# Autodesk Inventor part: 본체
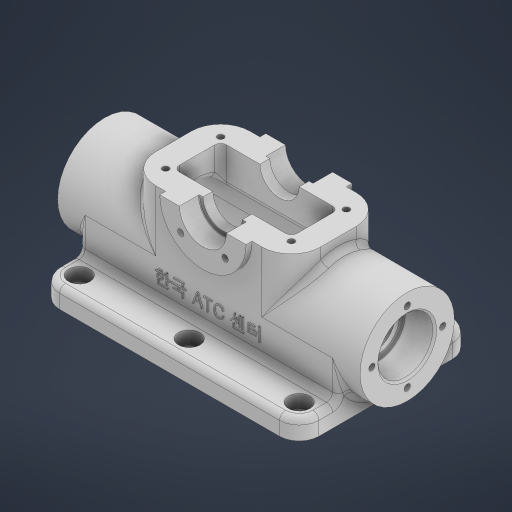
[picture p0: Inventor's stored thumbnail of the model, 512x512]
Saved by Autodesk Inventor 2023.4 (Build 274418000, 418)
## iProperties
Created: 2024-06
Part Number: 본체
Material: 알루미늄 6061
Document SubType Name: Modeling
Designer: Edu03
Density: 2.7 g/cm^3
Appearance: 기본값
Mass: 551.012 g
Surface Area: 614.152 cm^2
Volume: 204.079 cm^3
Author: Edu03
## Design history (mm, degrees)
sketch "스케치1"
  geometry: L1 (-94.718, 0)-(94.718, 0); L2 (-77, 24)-(-77, 14); L3 (-77, 14)-(-62, 14); L4 (-62, 14)-(-62, 11); L5 (-62, 11)-(-60, 11); L6 (-60, 11)-(-60, 18); L7 (-60, 18)-(60, 18); L8 (60, 18)-(60, 11); L9 (60, 11)-(62, 11); L10 (62, 11)-(62, 14); L11 (62, 14)-(77, 14); L12 (77, 14)-(77, 24); L13 (77, 24)-(-77, 24); 3 further points
  constraints: 26 end point, 9 perpendicular, 4 point on line, 2 midpoint, 1 coincident, 1 collinear, 1 horizontal, 1 vertical, 1 vertical alignment
  dimensions: "d0" = 154 distance of L12.end L2.start; "d1" = 15 distance of L2.end L3.end; "d2" = 15 distance of L10.end L11.end; "d3" = 120 distance of L6.end L7.end; "d4" = 48 diameter of L13 L1; "d5" = 22 diameter of L5 L1; "d6" = 28 diameter of L3 L1; "d7" = 6 distance between parallel lines of L13 L7
revolve "회전1" sketch "스케치1" stored, may be unused: angle "d8" = 90 deg
node "작업 평면1"
sketch "스케치2"
  geometry: L1 (44, -18)-(44, -28); L2 (44, -28)-(-44, -28); L3 (-44, -28)-(-44, -18); L4 (-24, -18)-(-24, 0); L5 (24, -18)-(24, 0); L6 (24, -18)-(44, -18); L7 (-44, -18)-(-24, -18); A1 r 24 centre (0, 0) between (-24, 0) and (24, 0) reference; 3 further points
  constraints: 14 end point, 3 parallel, 2 horizontal, 2 horizontal alignment, 2 perpendicular, 2 point on circle, 2 tangent, 2 vertical, 2 vertical alignment, 1 midpoint
  dimensions: "d10" = 88 distance of L1.end L2.end; "d12" = 28 distance from line of A1.centre L2; "d13" = 10 distance between parallel lines of L2 L6
extrude "돌출1" join sketch "스케치2" distance "d14" = 132; taper "d15" = 0 deg
node "작업 평면2"
sketch "스케치3"
  geometry: L1 (44, -28)-(-44, -28) reference; L2 (-18, -28)-(-18, 0); L3 (18, -28)-(18, 0); A1 r 18 centre (0, 0) between (18, 0) and (-18, 0) reference; 1 further point
  constraints: 4 end point, 2 point on circle, 2 point on line, 2 tangent, 2 vertical
extrude "돌출2" cut sketch "스케치3" distance "d17" = 120; taper "d18" = 0 deg
node "작업 평면3"
node "작업 평면4"
sketch "스케치5"
  geometry: L1 (24, 20)-(108, 20); L2 (108, 20)-(108, 68); L3 (108, 68)-(24, 68); L4 (24, 68)-(24, 20); L5 (143, 20)-(143, 68) reference; L6 (-11, 20)-(-11, 68) reference; L7 (0, 20)-(132, 20) reference; L8 (0, 20)-(0, 68) reference; L9 (0, 68)-(132, 68) reference; L10 (132, 68)-(132, 20) reference; 3 further points
  constraints: 8 end point, 2 midpoint, 2 parallel, 1 horizontal, 1 horizontal alignment, 1 perpendicular, 1 point on line, 1 vertical alignment
  dimensions: "d22" = 84 distance of L1.start L1.end
extrude "돌출3" join sketch "스케치5" stored distance "d24" = 120; taper "d25" = 0 deg
sketch "스케치6"
  geometry: L1 (36, -56)-(96, -56); L2 (96, -56)-(96, -32); L3 (96, -32)-(36, -32); L4 (36, -32)-(36, -56); L5 (36, -56)-(96, -32); L6 (96, -56)-(36, -32); 1 further point
  constraints: 12 end point, 2 midpoint, 2 parallel, 1 horizontal, 1 perpendicular
  dimensions: "d26" = 60 distance of L2.end L3.end; "d27" = 24 distance between parallel lines of L3 L1
extrude "돌출4" cut sketch "스케치6" extent not by distance; stored distance "d28" = 10; taper "d29" = 0 deg
sketch "스케치9"
  geometry: L1 (36, 49)-(96, 49) reference; C1 r 22 at (66, 49); 3 further points
  constraints: 1 centre point, 1 midpoint
  dimensions: "d37" = 44 diameter of C1
extrude "돌출5" join sketch "스케치9" distance "d38" = 3; taper "d39" = 0 deg
sketch "스케치11"
  geometry: A1 r 22 centre (66, 49) between (44, 49) and (88, 49) reference; 2 further points
  constraints: 1 coincident
hole "구멍2" sketch "스케치11" at (66, 49) diameter "d40" = 20; stored, may be unused: countersink angle "d44" = 90 deg, drill point angle "d46" = 0 deg; dims "d41" = 6, "d42" = 24, "d43" = 10, "d45" = 8
sketch "스케치12" dims "d47" = 32
  geometry: L1 (66, 49)-(54.686, 37.686); L2 (66, 49)-(66, 53.677); A1 r 12 centre (66, 49) between (54, 49) and (78, 49) reference; 2 further points
  constraints: 4 end point, 1 coincident, 1 vertical, 3 other
  dimensions: "d48" = 45 deg angle of L2 L1
hole "구멍3" sketch "스케치12" at (54.686, 37.686) diameter "d49" = 3.242; stored, may be unused: countersink angle "d53" = 90 deg, drill point angle "d55" = 118 deg; dims "d50" = 8, "d51" = 24, "d52" = 10, "d54" = 10
sketch "스케치13"
  geometry: L1 (34, -30)-(98, -30); L2 (98, -30)-(98, -58); L3 (98, -58)-(34, -58); L4 (34, -58)-(34, -30); L5 (54, -17)-(78, -17) reference; L6 (108, -20)-(108, -68) reference; 5 further points
  constraints: 8 end point, 4 midpoint, 2 parallel, 1 horizontal, 1 horizontal alignment, 1 perpendicular, 1 vertical alignment
  dimensions: "d56" = 28 distance of L1.end L2.end; "d57" = 64 distance of L1.start L1.end
hole "구멍4" sketch "스케치13" at (34, -58), (98, -58), (98, -30), (34, -30) diameter "d58" = 3.242; stored, may be unused: countersink angle "d62" = 90 deg, drill point angle "d64" = 118 deg; dims "d59" = 8, "d60" = 4, "d61" = 2, "d63" = 10
sketch "스케치14"
  geometry: A1 r 18 centre (0, 0) between (12, 13.416) and (-12, 13.416); A2 r 18 centre (0, 0) between (12, 13.416) and (-12, 13.416) reference; 2 further points
  constraints: 1 centre point, 1 coincident, 1 point on circle, 1 vertical alignment
  dimensions: "d65" = 36 diameter of A1
hole "구멍5" sketch "스케치14" at (0, 18) diameter "d66" = 3.242; stored, may be unused: countersink angle "d70" = 90 deg, drill point angle "d72" = 118 deg; dims "d67" = 8, "d68" = 4, "d69" = 2, "d71" = 10
sketch "스케치15" dims "d76" = 36
  geometry: 3 further points
  constraints: 2 vertical alignment, 1 coincident, 2 other
hole "구멍6" sketch "스케치15" at (0, 18) diameter "d77" = 3.242; stored, may be unused: countersink angle "d81" = 90 deg, drill point angle "d83" = 118 deg; dims "d78" = 8, "d79" = 4, "d80" = 2, "d82" = 10
fillet "모깎기1" dims "d87" = 3
fillet "모깎기2" dims "d88" = 3
sketch "스케치16"
  geometry: L1 (10, 10)-(122, 10); 2 further points
  constraints: 2 end point, 1 horizontal, 1 midpoint, 1 vertical alignment
  dimensions: "d89" = 112 distance of L1.start L1.end; "d90" = 34 distance from line of point (66, 44) L1
hole "구멍7" sketch "스케치16" at (10, 10), (66, 10), (122, 10) diameter "d91" = 6.6; stored, may be unused: countersink angle "d95" = 90 deg, drill point angle "d97" = 0 deg; dims "d92" = 8, "d93" = 11, "d94" = 6.6, "d96" = 8
fillet "모깎기3" dims "d98" = 10
fillet "모깎기4" dims "d99" = 3
sketch "스케치17"
  geometry: L1 (24, -28)-(14, -28) reference; 2 further points
  constraints: 1 vertical alignment, 1 other
  dimensions: "d100" = 20 distance from line of L1 point (-42, -8)
feature "엠보싱1" sketch "스케치17" dims "d0" = 154, "d1" = 15, "d2" = 15, "d3" = 120, "d4" = 48, "d5" = 22, "d6" = 28, "d7" = 6, "d101" = 0.5, "d102" = 0
fillet "모깎기5" dims "d103" = 3
fillet "모깎기6" dims "d104" = 3
fillet "모깎기7" dims "d105" = 15
fillet "모깎기8" dims "d106" = 3
chamfer "모따기1" distance "d107" = 1; stored, may be unused: second distance "d108" = 2, angle "d109" = 45 deg
fillet "모깎기9" dims "d110" = 0.3
node "솔리드1"
mirror "미러2"
mirror "미러3"
mirror "미러4"
mirror "미러5"
pattern_circular "원형 패턴1" dims angle "d74" = 360 deg
pattern_circular "원형 패턴2" dims angle "d85" = 360 deg
mirror "미러6"
node "투영된 루프2"
feature "A9D066F2-1C7D-4E18-AEED-F7BC21143FA4" dims "d49" = 3.242, "d50" = 8, "d51" = 24, "d52" = 10, "d53" = 90 deg, "d54" = 10, "d55" = 118 deg
other parameters: "d9" = -11, "d16" = -6, "d21" = -59
